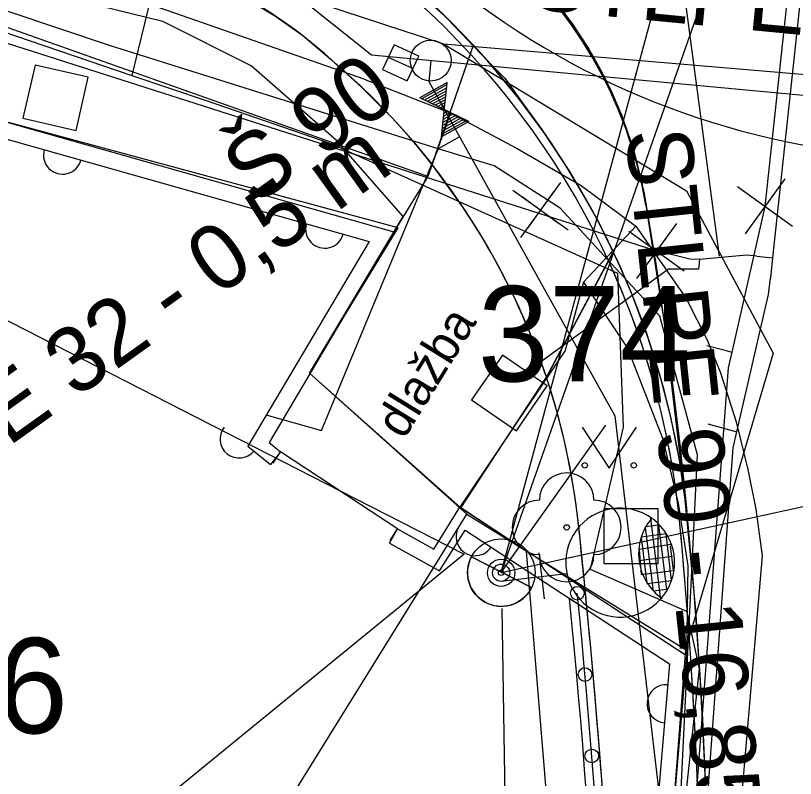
# Model space of a CAD drawing. Extents: x -643342 to -638635, y -1201752 to -1189948.
# Drawn here: x -639509.69 to -639495.38, y -1192739.55 to -1192725.54 of the extents above; entities that cross this region are included whole.
import ezdxf

# ---------------------------------------------------------------- set-up
doc = ezdxf.new("R2010")
doc.units = 0
for name, color, linetype in [('-zbytky_kruháče', 7, 'Continuous'), ('2', 7, 'Continuous'), ('IS_EL_NN_NADZEMNÍ', 7, 'Continuous'), ('IS_EL_NN_PODZEMNÍ', 7, 'Continuous'), ('IS_PLYN_STL', 7, 'Continuous'), ('IS_TELEF_MISTNI_ZAMERENO', 7, 'Continuous'), ('IS_VODOVOD_PRIPOJKA DOMOVNÍ', 7, 'Continuous'), ('IS_VODOVOD_PRIPOJKA HYDRANT', 7, 'Continuous'), ('IS_VODOVOD_VAS', 7, 'Continuous'), ('IS_VODOVOD_ZRUSENY', 7, 'Continuous'), ('K-HRANICE_KN', 7, 'Continuous'), ('K-ČÍSLA_PARCEL', 7, 'Continuous'), ('N-CHODNIK', 7, 'Continuous'), ('N-OBVOD STAVBY 06', 7, 'Continuous'), ('N-oploceni', 7, 'Continuous'), ('N-rusene_vedeni', 7, 'Continuous'), ('N-SILNICE', 7, 'Continuous'), ('N-SRAFY_PLOCHY', 7, 'Continuous'), ('RWE_STL_PRIPOJKY', 7, 'Continuous'), ('RWE_STL_RADY', 7, 'Continuous'), ('RWE_STL_UZAVERY', 7, 'Continuous'), ('tomaštík - Džuganovi - Vrstva 36', 7, 'Continuous'), ('Vrstva 13', 7, 'Continuous'), ('Z-hrany_a_čáry', 7, 'Continuous'), ('Z-popisy', 7, 'Continuous'), ('Z-sloupy', 7, 'Continuous'), ('Z-stromy', 7, 'Continuous'), ('Z-vchody_vjezdy', 7, 'Continuous'), ('Z-VO_rozhlas', 7, 'Continuous'), ('Z-značky', 7, 'Continuous'), ('Z-šachty_poklopy', 7, 'Continuous')]:
    doc.layers.add(name, color=color, linetype=linetype)

# ---------------------------------------------------------------- blocks, each defined once
blk = doc.blocks.new('SKUL')
at = {"layer": 'Vrstva 13'}
for p, q in [((-38.5, 54.5), (38.5, -54.5)), ((38.5, 54.5), (-38.5, -54.5)), ((-38.5, 54.5), (38.5, 54.5)), ((-35.3, 50), (35.3, 50)), ((-31.1, 44), (31.1, 44)), ((-26.8, 38), (26.8, 38)), ((-22.6, 32), (22.6, 32)), ((-18.4, 26), (18.4, 26)), ((-14.1, 20), (14.1, 20)), ((-9.9, 14), (9.9, 14)), ((-5.7, 8), (5.7, 8)), ((-1.4, 2), (1.4, 2)), ((-9.9, -14), (9.9, -14)), ((-5.7, -8), (5.7, -8)), ((-1.4, -2), (1.4, -2)), ((-26.8, -38), (26.8, -38)), ((-22.6, -32), (22.6, -32)), ((-18.4, -26), (18.4, -26)), ((-14.1, -20), (14.1, -20)), ((-38.5, -54.5), (38.5, -54.5)), ((-36, -50), (35.3, -50)), ((-31.1, -44), (31.1, -44))]:
    blk.add_line(p, q, dxfattribs=at)
blk = doc.blocks.new('A$C48307C76')
at = {"layer": 'N-oploceni'}
blk.add_circle((0, 0), 0.125, dxfattribs=at)

msp = doc.modelspace()

# ---------------------------------------------------------------- linework, layer by layer
at = {"layer": '-zbytky_kruháče'}
msp.add_arc((-639492.588, -1192713.663), 14.5, 152.4602, 296.3322, dxfattribs=at)
at = {"layer": '2'}
msp.add_circle((-639502.076, -1192726.369), 0.375, dxfattribs=at)
at = {"layer": 'IS_EL_NN_NADZEMNÍ'}
for p, q in [((-639500.78, -1192735.77), (-639489.5, -1192694.06)), ((-639535.66, -1192717.92), (-639503.74, -1192734.27)), ((-639500.78, -1192735.77), (-639472.79, -1192729.64)), ((-639503.74, -1192734.27), (-639501.46, -1192735.43)), ((-639500.77, -1192736.43), (-639500.31, -1192766.84))]:
    msp.add_line(p, q, dxfattribs=at)
for points in [[(-639500.783, -1192735.773), (-639485.819, -1192693.156)], [(-639501.327, -1192735.478), (-639500.223, -1192736.043)], [(-639500.223, -1192736.043), (-639501.327, -1192735.478)]]:
    msp.add_lwpolyline(points, dxfattribs=at)
msp.add_circle((-639500.78, -1192735.77), 0.62, dxfattribs=at)
for centre, radius, start, end in [((-639500.78, -1192735.77), 0.62, 151.974, 332.893), ((-639500.8, -1192735.747), 0.649, 331.916, 332.8402)]:
    msp.add_arc(centre, radius, start, end, dxfattribs=at)
at = {"layer": 'IS_EL_NN_PODZEMNÍ'}
for p, q in [((-639500.78, -1192735.77), (-639498.86, -1192733.06)), ((-639501.46, -1192735.43), (-639513.06, -1192744.91))]:
    msp.add_line(p, q, dxfattribs=at)
at = {"layer": 'IS_PLYN_STL'}
for points in [[(-639501.39, -1192783.75), (-639500.989, -1192780.093), (-639500.16, -1192772.52), (-639499.45, -1192766.45), (-639499.2, -1192762.17), (-639498.55, -1192754.89), (-639497.68, -1192743.88), (-639497.18, -1192733.61), (-639497.87, -1192731.06), (-639499.7, -1192729.08), (-639500.91, -1192728.3), (-639501.94, -1192727.99), (-639507.97, -1192726.09), (-639511.7, -1192724.84), (-639512.15, -1192724.73), (-639515.02, -1192723.8), (-639520.31, -1192722.34), (-639520.46, -1192722.3), (-639520.92, -1192722.11)], [(-639505.08, -1192732.88), (-639504.08, -1192733.16), (-639501.94, -1192727.99)]]:
    msp.add_lwpolyline(points, dxfattribs=at)
at = {"layer": 'IS_TELEF_MISTNI_ZAMERENO'}
for p, q in [((-639504.65, -1192714.57), (-639507.56, -1192726.64)), ((-639504.65, -1192714.57), (-639507.56, -1192726.64)), ((-639509.95, -1192725.83), (-639507.56, -1192726.64)), ((-639507.56, -1192726.64), (-639506.18, -1192727.11)), ((-639506.18, -1192727.11), (-639503.91, -1192727.89)), ((-639503.91, -1192727.89), (-639498.65, -1192730.27)), ((-639503.91, -1192727.89), (-639498.65, -1192730.27)), ((-639498.65, -1192730.27), (-639498.54, -1192733.1)), ((-639498.54, -1192733.1), (-639499.15, -1192735.71)), ((-639499.15, -1192735.71), (-639497.38, -1192736.48)), ((-639497.38, -1192736.48), (-639497.15, -1192737.53)), ((-639497.15, -1192737.53), (-639498.18, -1192747.3)), ((-639497.15, -1192737.53), (-639498.18, -1192747.3))]:
    msp.add_line(p, q, dxfattribs=at)
at = {"layer": 'IS_VODOVOD_PRIPOJKA DOMOVNÍ'}
msp.add_lwpolyline([(-639497.14, -1192730.02), (-639497.16, -1192730.2), (-639497.71, -1192730.2), (-639500.525, -1192732.24)], dxfattribs=at)
at = {"layer": 'IS_VODOVOD_PRIPOJKA HYDRANT'}
for points in [[(-639497.01, -1192731.6), (-639496.72, -1192731.676), (-639496.55, -1192731.72)], [(-639496.99, -1192733.04), (-639496.701, -1192733.119), (-639496.454, -1192733.187)]]:
    msp.add_lwpolyline(points, dxfattribs=at)
at = {"layer": 'IS_VODOVOD_VAS'}
for points in [[(-639513.05, -1192632.38), (-639511.6, -1192653.11), (-639509.94, -1192661.802), (-639509.17, -1192665.92), (-639508.128, -1192674.317), (-639507.037, -1192678.26), (-639504.087, -1192695.682), (-639502.448, -1192705.362), (-639494.166, -1192711.159), (-639494.54, -1192716.007), (-639495.94, -1192729.045), (-639496.55, -1192731.72), (-639496.617, -1192732.012), (-639498.895, -1192762.442), (-639502.42, -1192797.68), (-639508.622, -1192858.606)], [(-639503.85, -1192695.64), (-639502.23, -1192705.222), (-639493.917, -1192711.041), (-639494.301, -1192716.029), (-639495.801, -1192729.991)], [(-639496.09, -1192729.96), (-639496.274, -1192729.942), (-639497.14, -1192730.02), (-639497.319, -1192730.013), (-639497.98, -1192729.852), (-639517.2, -1192723.7), (-639533.16, -1192716.44), (-639534.26, -1192716.19), (-639547.57, -1192711.28), (-639564.69, -1192707.49), (-639577.32, -1192705.32), (-639579.08, -1192705.18), (-639581.13, -1192706.12), (-639584.92, -1192706.29)], [(-639496.09, -1192729.96), (-639495.801, -1192729.991)], [(-639495.801, -1192729.991), (-639495.841, -1192730.366)], [(-639508.361, -1192858.606), (-639507.808, -1192853.178), (-639506.048, -1192835.895), (-639505.024, -1192825.834), (-639502.574, -1192801.785), (-639502.3, -1192799.09), (-639501.659, -1192792.67), (-639499.852, -1192774.557), (-639499.821, -1192774.244), (-639499.787, -1192773.906), (-639498.645, -1192762.458), (-639497.227, -1192743.11), (-639497.188, -1192742.573), (-639497.153, -1192742.104), (-639496.521, -1192733.479), (-639496.454, -1192733.187), (-639495.873, -1192730.664), (-639495.841, -1192730.366)]]:
    msp.add_lwpolyline(points, dxfattribs=at)
at = {"layer": 'IS_VODOVOD_ZRUSENY'}
msp.add_lwpolyline([(-639515.23, -1192614.43), (-639514.98, -1192614.84), (-639507.86, -1192661.34), (-639506.03, -1192670.84), (-639505.88, -1192671.62), (-639500.98, -1192698.45), (-639496.78, -1192729.96)], dxfattribs=at)
at = {"layer": 'K-HRANICE_KN'}
for p, q in [((-639512.37, -1192722.6), (-639501.84, -1192726.06)), ((-639501.84, -1192726.06), (-639484.21, -1192727.56)), ((-639501.84, -1192726.06), (-639497.38, -1192728.76)), ((-639502.67, -1192729.44), (-639510.81, -1192727.24)), ((-639497.38, -1192728.76), (-639495.79, -1192731.74)), ((-639504.3, -1192732.11), (-639502.67, -1192729.44)), ((-639495.79, -1192731.74), (-639497.4, -1192737.18)), ((-639501.41, -1192734.7), (-639504.3, -1192732.11)), ((-639509.52, -1192747.76), (-639501.41, -1192734.7)), ((-639501.41, -1192734.7), (-639497.4, -1192737.18)), ((-639497.4, -1192737.18), (-639498.81, -1192755.44))]:
    msp.add_line(p, q, dxfattribs=at)
at = {"layer": 'N-CHODNIK'}
for points in [[(-639502.05, -1192728.275), (-639502.13, -1192728.5), (-639502.75, -1192729.51), (-639504.3, -1192732.11), (-639502.154, -1192734.033), (-639501.53, -1192734.592), (-639499.952, -1192732.179)], [(-639501.436, -1192729.129), (-639502.05, -1192728.275)]]:
    msp.add_lwpolyline(points, dxfattribs=at)
for centre, radius, start, end in [((-639513.295, -1192736.862), 14.158, 25.8231, 33.1082), ((-639513.841, -1192736.919), 14.675, 18.8422, 25.0948)]:
    msp.add_arc(centre, radius, start, end, dxfattribs=at)
at = {"layer": 'N-OBVOD STAVBY 06'}
for points in [[(-639502.579, -1192729.232), (-639503.805, -1192727.835), (-639505.37, -1192726.464), (-639506.99, -1192725.648), (-639508.145, -1192725.368), (-639509.676, -1192725.206), (-639510.069, -1192725.158)], [(-639500.319, -1192735.379), (-639501.522, -1192734.58), (-639501.522, -1192734.58), (-639504.3, -1192732.11), (-639502.579, -1192729.232)], [(-639501.67, -1192780.46), (-639501.67, -1192780.46), (-639500.56, -1192772.43), (-639500.37, -1192770.844), (-639499.75, -1192766.35), (-639501.075, -1192766.21), (-639500.65, -1192762.336), (-639499.361, -1192762.432), (-639499.064, -1192758.144), (-639498.745, -1192753.539), (-639498.595, -1192751.279), (-639498.595, -1192751.279), (-639499.424, -1192751.305), (-639499.616, -1192745.247), (-639499.725, -1192743.019), (-639499.783, -1192741.836), (-639500.319, -1192735.379)]]:
    msp.add_lwpolyline(points, dxfattribs=at)
at = {"layer": 'N-oploceni'}
msp.add_arc((-639647.046, -1192750.754), 148.382, 0.05221, 5.64877, dxfattribs=at)
at = {"layer": 'N-rusene_vedeni'}
for p, q in [((-639499.694, -1192728.606), (-639500.425, -1192729.62)), ((-639495.574, -1192728.538), (-639496.306, -1192729.552)), ((-639500.566, -1192728.747), (-639499.553, -1192729.479)), ((-639499.82, -1192728.781), (-639500.299, -1192729.445)), ((-639496.447, -1192728.679), (-639495.433, -1192729.411)), ((-639500.392, -1192728.873), (-639499.728, -1192729.353)), ((-639497.565, -1192729.357), (-639498.296, -1192730.371)), ((-639498.437, -1192729.498), (-639497.424, -1192730.23))]:
    msp.add_line(p, q, dxfattribs=at)
at = {"layer": 'N-SILNICE'}
for p, q in [((-639502.05, -1192728.275), (-639501.292, -1192726.086)), ((-639499.952, -1192732.179), (-639498.725, -1192729.879)), ((-639499.525, -1192736.245), (-639499.204, -1192736.455))]:
    msp.add_line(p, q, dxfattribs=at)
for centre, radius, start, end in [((-639506.015, -1192730.304), 8, 9.4731, 90.8671), ((-639509.33, -1192732.23), 8, 47.2487, 86.6063), ((-639512.285, -1192736.291), 15, 4.9967, 49.491), ((-639512.285, -1192736.291), 14.85, 4.9967, 49.491), ((-639512.285, -1192736.291), 13, 4.9967, 49.491), ((-639581.965, -1192742.977), 85, 354.39361, 9.47307), ((-639581.965, -1192742.977), 84.85, 354.39361, 5.48049), ((-639581.965, -1192742.977), 85, 354.39361, 5.48049), ((-639647.046, -1192750.754), 148.532, 0.05221, 6.02687), ((-639647.046, -1192750.754), 148.232, 0.05221, 5.61695)]:
    msp.add_arc(centre, radius, start, end, dxfattribs=at)
at = {"layer": 'N-SRAFY_PLOCHY'}
for p, q in [((-639501.775, -1192725.588), (-639502.621, -1192724.829)), ((-639505.447, -1192725.235), (-639504.923, -1192725.552)), ((-639499.884, -1192725.165), (-639499.485, -1192725.682)), ((-639501.024, -1192726.382), (-639501.891, -1192725.476)), ((-639504.923, -1192725.552), (-639504.422, -1192725.911)), ((-639501.296, -1192726.098), (-639501.775, -1192725.588)), ((-639499.485, -1192725.682), (-639499.181, -1192726.144)), ((-639504.422, -1192725.911), (-639503.899, -1192726.355)), ((-639502.05, -1192728.275), (-639501.292, -1192726.086)), ((-639502.05, -1192728.275), (-639501.296, -1192726.098)), ((-639501.292, -1192726.086), (-639501.024, -1192726.382)), ((-639499.181, -1192726.144), (-639498.88, -1192726.685)), ((-639503.899, -1192726.355), (-639503.337, -1192726.86)), ((-639501.024, -1192726.382), (-639500.715, -1192726.691)), ((-639500.464, -1192727.058), (-639501.024, -1192726.382)), ((-639500.715, -1192726.691), (-639500.369, -1192727.18)), ((-639498.88, -1192726.685), (-639498.574, -1192727.364)), ((-639503.337, -1192726.86), (-639502.768, -1192727.435)), ((-639499.993, -1192727.695), (-639500.464, -1192727.058)), ((-639500.369, -1192727.18), (-639500.034, -1192727.636)), ((-639498.574, -1192727.364), (-639498.34, -1192728.048)), ((-639502.768, -1192727.435), (-639502.402, -1192727.845)), ((-639500.034, -1192727.636), (-639499.651, -1192728.214)), ((-639499.523, -1192728.408), (-639499.993, -1192727.695)), ((-639502.402, -1192727.845), (-639502.05, -1192728.275)), ((-639498.34, -1192728.048), (-639498.155, -1192728.812)), ((-639499.651, -1192728.214), (-639499.267, -1192728.856)), ((-639501.873, -1192728.507), (-639502.05, -1192728.275)), ((-639501.436, -1192729.129), (-639502.05, -1192728.275)), ((-639501.436, -1192729.129), (-639501.873, -1192728.507)), ((-639499.011, -1192729.305), (-639499.523, -1192728.408)), ((-639498.155, -1192728.812), (-639497.945, -1192730.103)), ((-639499.267, -1192728.856), (-639499.011, -1192729.305)), ((-639498.124, -1192729.025), (-639497.799, -1192731.143)), ((-639501.096, -1192729.673), (-639501.436, -1192729.129)), ((-639499.011, -1192729.305), (-639498.827, -1192729.68)), ((-639498.642, -1192730.056), (-639499.011, -1192729.305)), ((-639500.842, -1192730.122), (-639501.096, -1192729.673)), ((-639498.827, -1192729.68), (-639498.725, -1192729.879)), ((-639498.725, -1192729.879), (-639499.952, -1192732.179)), ((-639498.725, -1192729.879), (-639498.813, -1192730.044)), ((-639498.813, -1192730.044), (-639499.952, -1192732.179)), ((-639498.386, -1192730.65), (-639498.642, -1192730.056)), ((-639497.945, -1192730.103), (-639497.776, -1192731.26)), ((-639500.551, -1192730.695), (-639500.842, -1192730.122)), ((-639498.088, -1192731.45), (-639498.386, -1192730.65)), ((-639500.313, -1192731.223), (-639500.551, -1192730.695)), ((-639500.113, -1192731.725), (-639500.313, -1192731.223)), ((-639497.799, -1192731.143), (-639497.43, -1192734.245)), ((-639497.776, -1192731.26), (-639497.631, -1192732.359)), ((-639497.846, -1192732.225), (-639498.088, -1192731.45)), ((-639499.952, -1192732.179), (-639500.113, -1192731.725)), ((-639497.664, -1192732.94), (-639497.846, -1192732.225)), ((-639497.631, -1192732.359), (-639497.504, -1192733.418)), ((-639497.504, -1192733.736), (-639497.664, -1192732.94)), ((-639497.504, -1192733.418), (-639497.375, -1192734.646)), ((-639497.375, -1192734.646), (-639497.504, -1192733.736)), ((-639497.43, -1192734.245), (-639497.218, -1192736.456)), ((-639497.218, -1192736.456), (-639497.087, -1192738.46)), ((-639497.087, -1192738.46), (-639497.005, -1192740.394))]:
    msp.add_line(p, q, dxfattribs=at)
msp.add_lwpolyline([(-639502.05, -1192728.275), (-639502.13, -1192728.5), (-639502.75, -1192729.51), (-639504.3, -1192732.11), (-639502.154, -1192734.033), (-639501.53, -1192734.592), (-639499.952, -1192732.179)], dxfattribs=at)
for centre, radius, start, end in [((-639506.088, -1192730.383), 8.079, 9.6799, 90.3442), ((-639513.295, -1192736.862), 14.158, 25.8231, 33.1082), ((-639512.285, -1192736.291), 15, 5.4805, 25.3075), ((-639512.285, -1192736.291), 14.85, 9.1909, 24.8765), ((-639512.285, -1192736.291), 14.85, 9.1909, 24.8765), ((-639513.841, -1192736.919), 14.675, 18.8422, 25.0948), ((-639512.285, -1192736.291), 13, 4.9967, 18.439), ((-639512.285, -1192736.291), 14.85, 5.4805, 9.1909), ((-639512.285, -1192736.291), 14.85, 5.4805, 9.1909), ((-639581.965, -1192742.977), 84.85, 359.02114, 5.48049), ((-639581.965, -1192742.977), 84.85, 359.02114, 5.48049), ((-639581.965, -1192742.977), 85, 359.01279, 5.48049), ((-639647.046, -1192750.754), 148.532, 2.50056, 6.02687)]:
    msp.add_arc(centre, radius, start, end, dxfattribs=at)
at = {"layer": 'RWE_STL_PRIPOJKY'}
for p, q in [((-639501.546, -1192727.768), (-639501.94, -1192727.99)), ((-639501.94, -1192727.99), (-639502.012, -1192728.163))]:
    msp.add_line(p, q, dxfattribs=at)
at = {"layer": 'RWE_STL_RADY'}
for points in [[(-639456.391, -1192717.157), (-639456.89, -1192717.146), (-639457.119, -1192717.369), (-639466.356, -1192717.248), (-639466.499, -1192728.212), (-639484.493, -1192728.011), (-639503.164, -1192726.268), (-639506.439, -1192723.649), (-639519.474, -1192721.668)], [(-639502.076, -1192726.369), (-639502.112, -1192726.754), (-639498.698, -1192732.892), (-639497.601, -1192742.26)]]:
    msp.add_lwpolyline(points, dxfattribs=at)
at = {"layer": 'Z-hrany_a_čáry'}
for p, q in [((-639503.3, -1192726.71), (-639527.524, -1192718.244)), ((-639502.13, -1192728.5), (-639509.83, -1192725.77)), ((-639503.3, -1192726.71), (-639501.72, -1192727.328)), ((-639510.82, -1192727.23), (-639502.75, -1192729.51)), ((-639501.715, -1192727.331), (-639502.13, -1192728.5)), ((-639501.72, -1192727.328), (-639500.491, -1192727.98)), ((-639510.902, -1192727.519), (-639503.207, -1192729.693)), ((-639500.491, -1192727.98), (-639499.311, -1192728.662)), ((-639502.13, -1192728.5), (-639502.75, -1192729.51)), ((-639499.311, -1192728.662), (-639498.31, -1192729.41)), ((-639502.75, -1192729.51), (-639505.04, -1192733.38)), ((-639498.31, -1192729.41), (-639499.27, -1192730.44)), ((-639498.31, -1192729.41), (-639497.388, -1192730.74)), ((-639503.207, -1192729.693), (-639505.43, -1192733.45)), ((-639499.27, -1192730.44), (-639499.61, -1192731.69)), ((-639499.27, -1192730.44), (-639498.462, -1192731.648)), ((-639497.388, -1192730.74), (-639497, -1192731.498)), ((-639497, -1192731.498), (-639496.757, -1192732.105)), ((-639498.462, -1192731.648), (-639497.824, -1192733.299)), ((-639499.61, -1192731.69), (-639501.538, -1192734.57)), ((-639496.757, -1192732.105), (-639496.466, -1192732.999)), ((-639496.466, -1192732.999), (-639496.256, -1192733.878)), ((-639505.04, -1192733.38), (-639504.83, -1192733.55)), ((-639497.824, -1192733.299), (-639497.531, -1192734.498)), ((-639505.43, -1192733.45), (-639505.019, -1192733.783)), ((-639504.83, -1192733.55), (-639505.019, -1192733.783)), ((-639496.256, -1192733.878), (-639496.111, -1192734.606)), ((-639497.531, -1192734.498), (-639497.359, -1192735.643)), ((-639502.018, -1192735.338), (-639501.538, -1192734.57)), ((-639501.538, -1192734.57), (-639497.38, -1192737.29)), ((-639496.111, -1192734.606), (-639495.99, -1192735.46)), ((-639502.829, -1192735.231), (-639502.684, -1192734.969)), ((-639502.684, -1192734.969), (-639502.018, -1192735.338)), ((-639501.914, -1192735.738), (-639501.446, -1192734.989)), ((-639501.446, -1192734.989), (-639497.694, -1192737.443)), ((-639502.829, -1192735.231), (-639501.914, -1192735.738)), ((-639495.99, -1192735.46), (-639497.82, -1192756.55)), ((-639497.359, -1192735.643), (-639497.38, -1192737.29)), ((-639497.38, -1192737.29), (-639498.67, -1192752.46)), ((-639497.694, -1192737.443), (-639498.969, -1192752.435))]:
    msp.add_line(p, q, dxfattribs=at)
for centre, start, end in [((-639508.833, -1192728.104), 164.2239, 344.2239), ((-639504.021, -1192729.463), 164.2239, 344.2239), ((-639505.594, -1192733.317), 140.985, 320.985), ((-639501.261, -1192735.11), 146.8133, 326.8133), ((-639497.756, -1192738.178), 85.139, 265.139)]:
    msp.add_arc(centre, 0.35, start, end, dxfattribs=at)
at = {"layer": 'Z-sloupy'}
for radius in [0.25, 0.158, 0.05]:
    msp.add_circle((-639500.783, -1192735.773), radius, dxfattribs=at)
at = {"layer": 'Z-stromy'}
msp.add_circle((-639499.58, -1192734.94), 0.05, dxfattribs=at)
for centre, start, end in [((-639499.58, -1192734.44), 0, 180), ((-639500.08, -1192734.94), 90, 270), ((-639499.08, -1192734.94), 270, 90), ((-639499.58, -1192735.44), 180, 0)]:
    msp.add_arc(centre, 0.5, start, end, dxfattribs=at)
at = {"layer": 'Z-vchody_vjezdy'}
for p, q in [((-639504.968, -1192733.759), (-639504.83, -1192733.55)), ((-639502.684, -1192734.969), (-639504.83, -1192733.55)), ((-639502.822, -1192735.178), (-639502.684, -1192734.969))]:
    msp.add_line(p, q, dxfattribs=at)
at = {"layer": 'Z-VO_rozhlas'}
for p, q in [((-639498.042, -1192734.77), (-639497.865, -1192736.22)), ((-639498.136, -1192734.925), (-639497.895, -1192734.894)), ((-639497.988, -1192736.113), (-639498.134, -1192734.944)), ((-639497.895, -1192734.894), (-639497.748, -1192736.082)), ((-639497.752, -1192735.061), (-639498.215, -1192735.118)), ((-639497.656, -1192735.918), (-639497.752, -1192735.061)), ((-639497.667, -1192735.255), (-639498.248, -1192735.347)), ((-639498.215, -1192735.118), (-639498.109, -1192735.973)), ((-639498.248, -1192735.347), (-639498.212, -1192735.802)), ((-639497.619, -1192735.729), (-639497.673, -1192735.277)), ((-639500.088, -1192735.407), (-639499.993, -1192736.252)), ((-639497.639, -1192735.476), (-639498.253, -1192735.552)), ((-639499.577, -1192735.795), (-639500.79, -1192735.931)), ((-639498.212, -1192735.802), (-639497.619, -1192735.729)), ((-639498.109, -1192735.973), (-639497.656, -1192735.918)), ((-639497.748, -1192736.082), (-639497.988, -1192736.113))]:
    msp.add_line(p, q, dxfattribs=at)
for centre, start, end in [((-639498.598, -1192735.587), 54.1332, 53.2855), ((-639497.26, -1192735.423), 139.3372, 235.245)]:
    msp.add_arc(centre, 1, start, end, dxfattribs=at)
at = {"layer": 'Z-značky'}
for p, q in [((-639499.298, -1192733.101), (-639498.798, -1192733.851)), ((-639498.798, -1192733.851), (-639498.298, -1192733.101))]:
    msp.add_line(p, q, dxfattribs=at)
for centre in [(-639499.248, -1192733.801), (-639498.349, -1192733.801)]:
    msp.add_circle(centre, 0.05, dxfattribs=at)
at = {"layer": 'Z-šachty_poklopy'}
for p, q in [((-639502.749, -1192726.078), (-639502.959, -1192726.532)), ((-639502.296, -1192726.287), (-639502.749, -1192726.078)), ((-639502.854, -1192726.305), (-639502.4, -1192726.514)), ((-639502.505, -1192726.741), (-639502.296, -1192726.287)), ((-639509.334, -1192726.45), (-639509.56, -1192727.424)), ((-639508.36, -1192726.676), (-639509.334, -1192726.45)), ((-639502.959, -1192726.532), (-639502.505, -1192726.741)), ((-639508.586, -1192727.65), (-639508.36, -1192726.676)), ((-639509.56, -1192727.424), (-639508.586, -1192727.65)), ((-639500.76, -1192731.775), (-639501.325, -1192732.6)), ((-639499.935, -1192732.34), (-639500.76, -1192731.775)), ((-639500.5, -1192733.165), (-639499.935, -1192732.34)), ((-639501.325, -1192732.6), (-639500.5, -1192733.165)), ((-639497.9, -1192734.6), (-639498.9, -1192734.6)), ((-639498.9, -1192734.6), (-639498.9, -1192735.6)), ((-639497.9, -1192735.6), (-639497.9, -1192734.6)), ((-639498.9, -1192735.6), (-639497.9, -1192735.6))]:
    msp.add_line(p, q, dxfattribs=at)

# ---------------------------------------------------------------- block references
at = {"layer": 'defpoints'}
for p, rotation in [((-639499.244, -1192737.642), 95.06956152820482), ((-639499.119, -1192739.137), 94.49035770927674)]:
    msp.add_blockref('A$C48307C76', p, dxfattribs=dict(at, rotation=rotation))
at = {"layer": 'N-oploceni', "rotation": -78.156169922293}
msp.add_blockref('A$C48307C76', (-639499.384, -1192736.149), dxfattribs=at)
at = {"layer": 'RWE_STL_UZAVERY', "xscale": 0.0075, "yscale": 0.0075, "rotation": -151.00000000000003}
msp.add_blockref('SKUL', (-639501.826, -1192727.269), dxfattribs=at)

# ---------------------------------------------------------------- texts
at = {"layer": 'K-ČÍSLA_PARCEL'}
for s, p in [('374', (-639501.21, -1192732.259)), ('26', (-639511.337, -1192738.72))]:
    msp.add_text(s, height=1.75, dxfattribs=at).set_placement(p)
at = {"layer": 'RWE_STL_RADY'}
for s, rotation, p in [('STLPE 110 - 75,71 m', 354.4856, (-639500.29, -1192725.414)), ('Š 90', 35.5673, (-639505.316, -1192729.055)), ('PE 32 - 0,5 m', 35.5673, (-639510.701, -1192734.09)), ('STLPE 90 - 16,85 m', 276.0055, (-639498.503, -1192727.668))]:
    msp.add_text(s, height=1.2, rotation=rotation, dxfattribs=at).set_placement(p)
at = {"layer": 'tomaštík - Džuganovi - Vrstva 36'}
msp.add_text('OCHRANNÁ TRUBKA ', height=1.25, rotation=83.0956, dxfattribs=at).set_placement((-639494.978, -1192751.335))
at = {"layer": 'Z-popisy'}
msp.add_text('dlažba', height=0.65, rotation=58.2504, dxfattribs=at).set_placement((-639502.568, -1192733.342))

doc.saveas('drawing.dxf')
